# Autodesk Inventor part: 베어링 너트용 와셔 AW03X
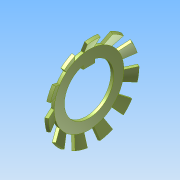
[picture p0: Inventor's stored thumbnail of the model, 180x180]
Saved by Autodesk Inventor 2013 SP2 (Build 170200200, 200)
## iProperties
Created: 2025-05
Part Number: 베어링 너트용 와셔 AW03X
Material: Generic
Document SubType Name: Modeling
Designer: a
Density: 1 g/cm^3
Author: a
변환 표준: STEP AP214IS
전처리기: Build: 200, Release: 2013 SP2 Update 6 - Date: Thu 07/17/2014
전송 단위: 밀리미터
불확실성: 0.01
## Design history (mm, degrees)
node "베어링 너트용 와셔 AW03X1"
body "Solid1"
node "기준1"
